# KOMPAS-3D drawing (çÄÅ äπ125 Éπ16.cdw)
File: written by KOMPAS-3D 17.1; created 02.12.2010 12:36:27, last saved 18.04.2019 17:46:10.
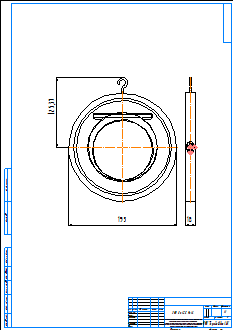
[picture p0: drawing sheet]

Sheet 1: A2, portrait

Title block, sheet 1: name: ЗОП Ду125 Ру16; material: Внимание! Данный продукт является объектом авторского права ООО «Торговый Дом АДЛ». / Запрещается изменение, копирование, распространение / (в том числе путем копирования на другие сайты и ресурсы в Интернете) / или любое иное использование информации и объектов без предварительного / согласия правообладателя (ООО «Торговый Дом АДЛ»).; scale: 1:1; sheets: 1; organisation: ООО "Торговый дом АДЛ"; sheet format: A2; stored path: \\adlc.lan\data\АДЛ_ПКД\3D-модели\ADL production\Клапаны обратные ГРАНЛОК\ЗОП\KOMPAS 2D\ЗОП Ду125 Ру16.cdw

Views: Спереди 1, Проекционный вид 2
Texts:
  bsv
  adl
Dimensions and other numbers on the sheet: 195; 18; 125,37; 1:1; 1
